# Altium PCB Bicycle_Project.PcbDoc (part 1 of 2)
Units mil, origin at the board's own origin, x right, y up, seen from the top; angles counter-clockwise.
Board outline 2480.32 x 3188.98 mil, 2 copper layers (Top Layer, Bottom Layer), stack 35.085 mil thick; 108 components, 96 nets, 359 pads, 129 vias.
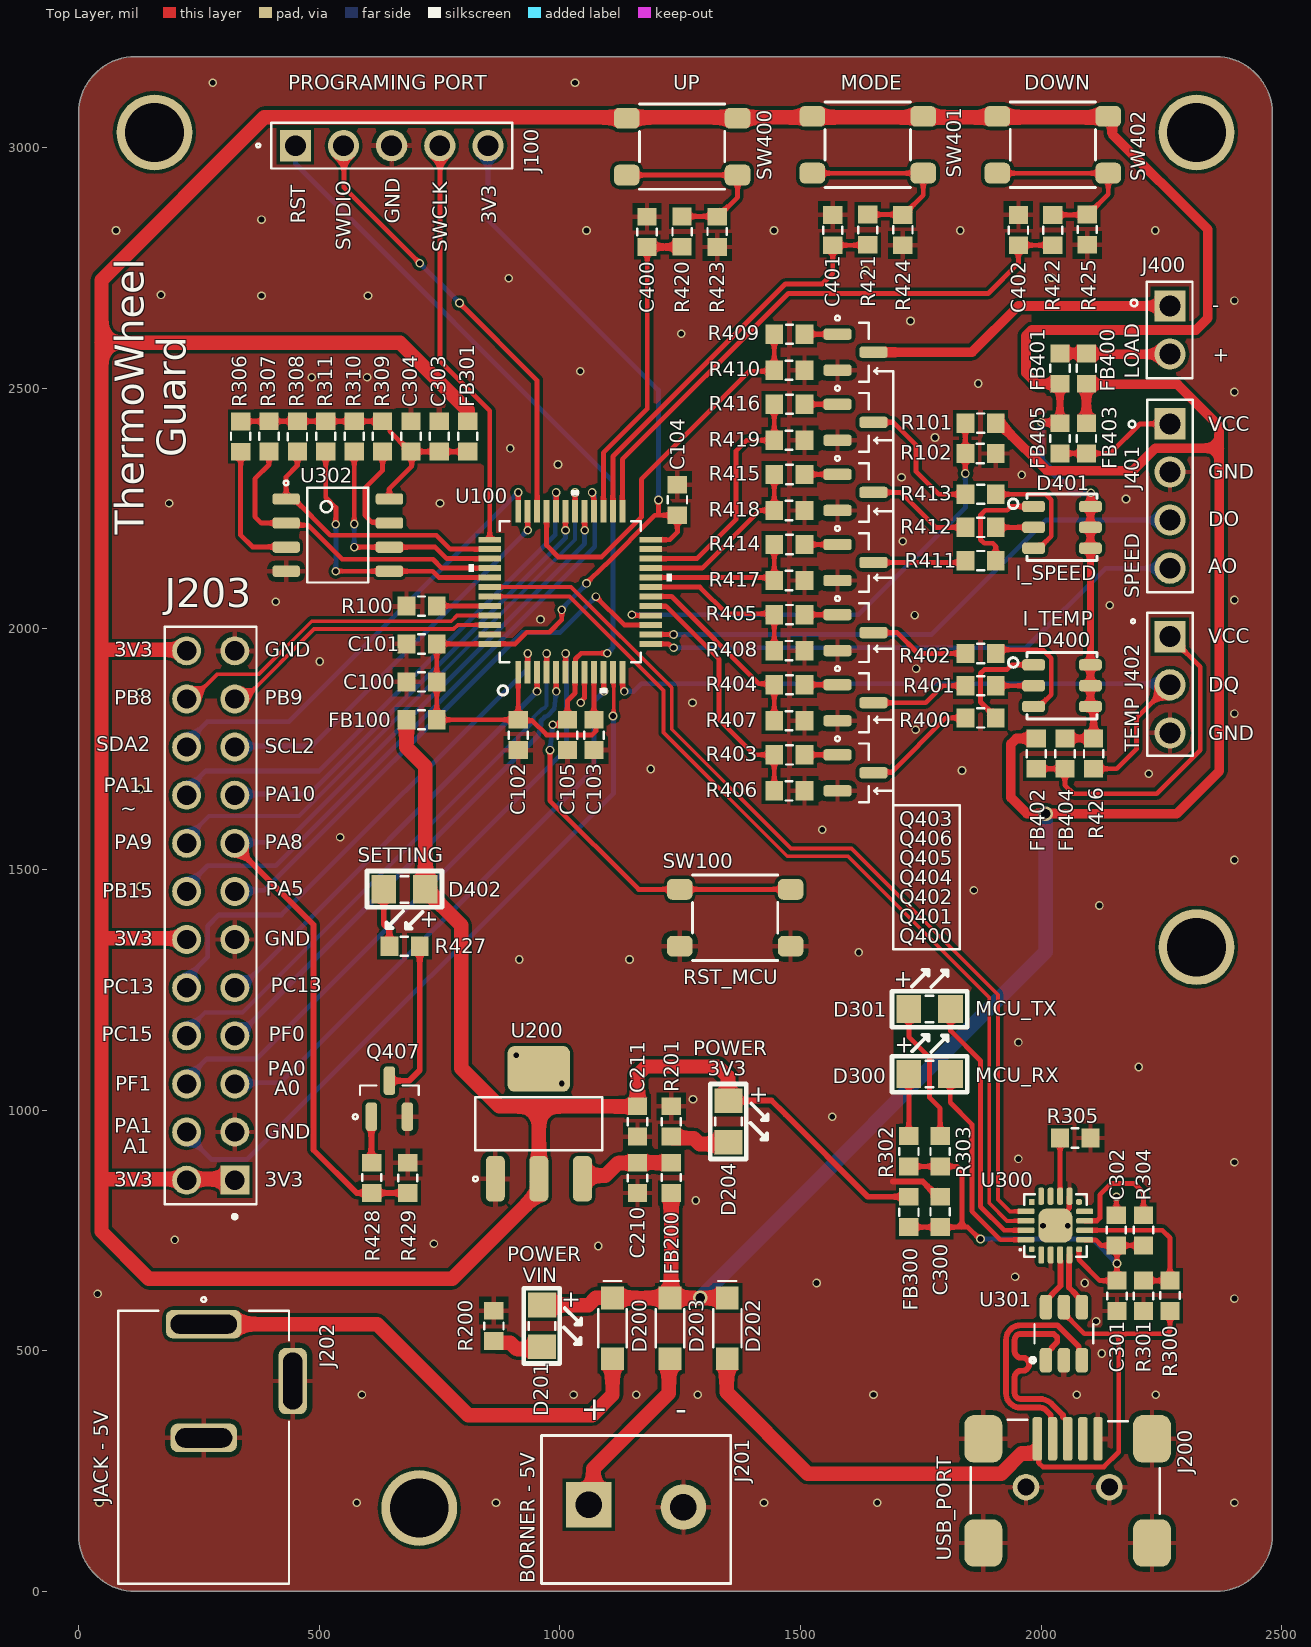
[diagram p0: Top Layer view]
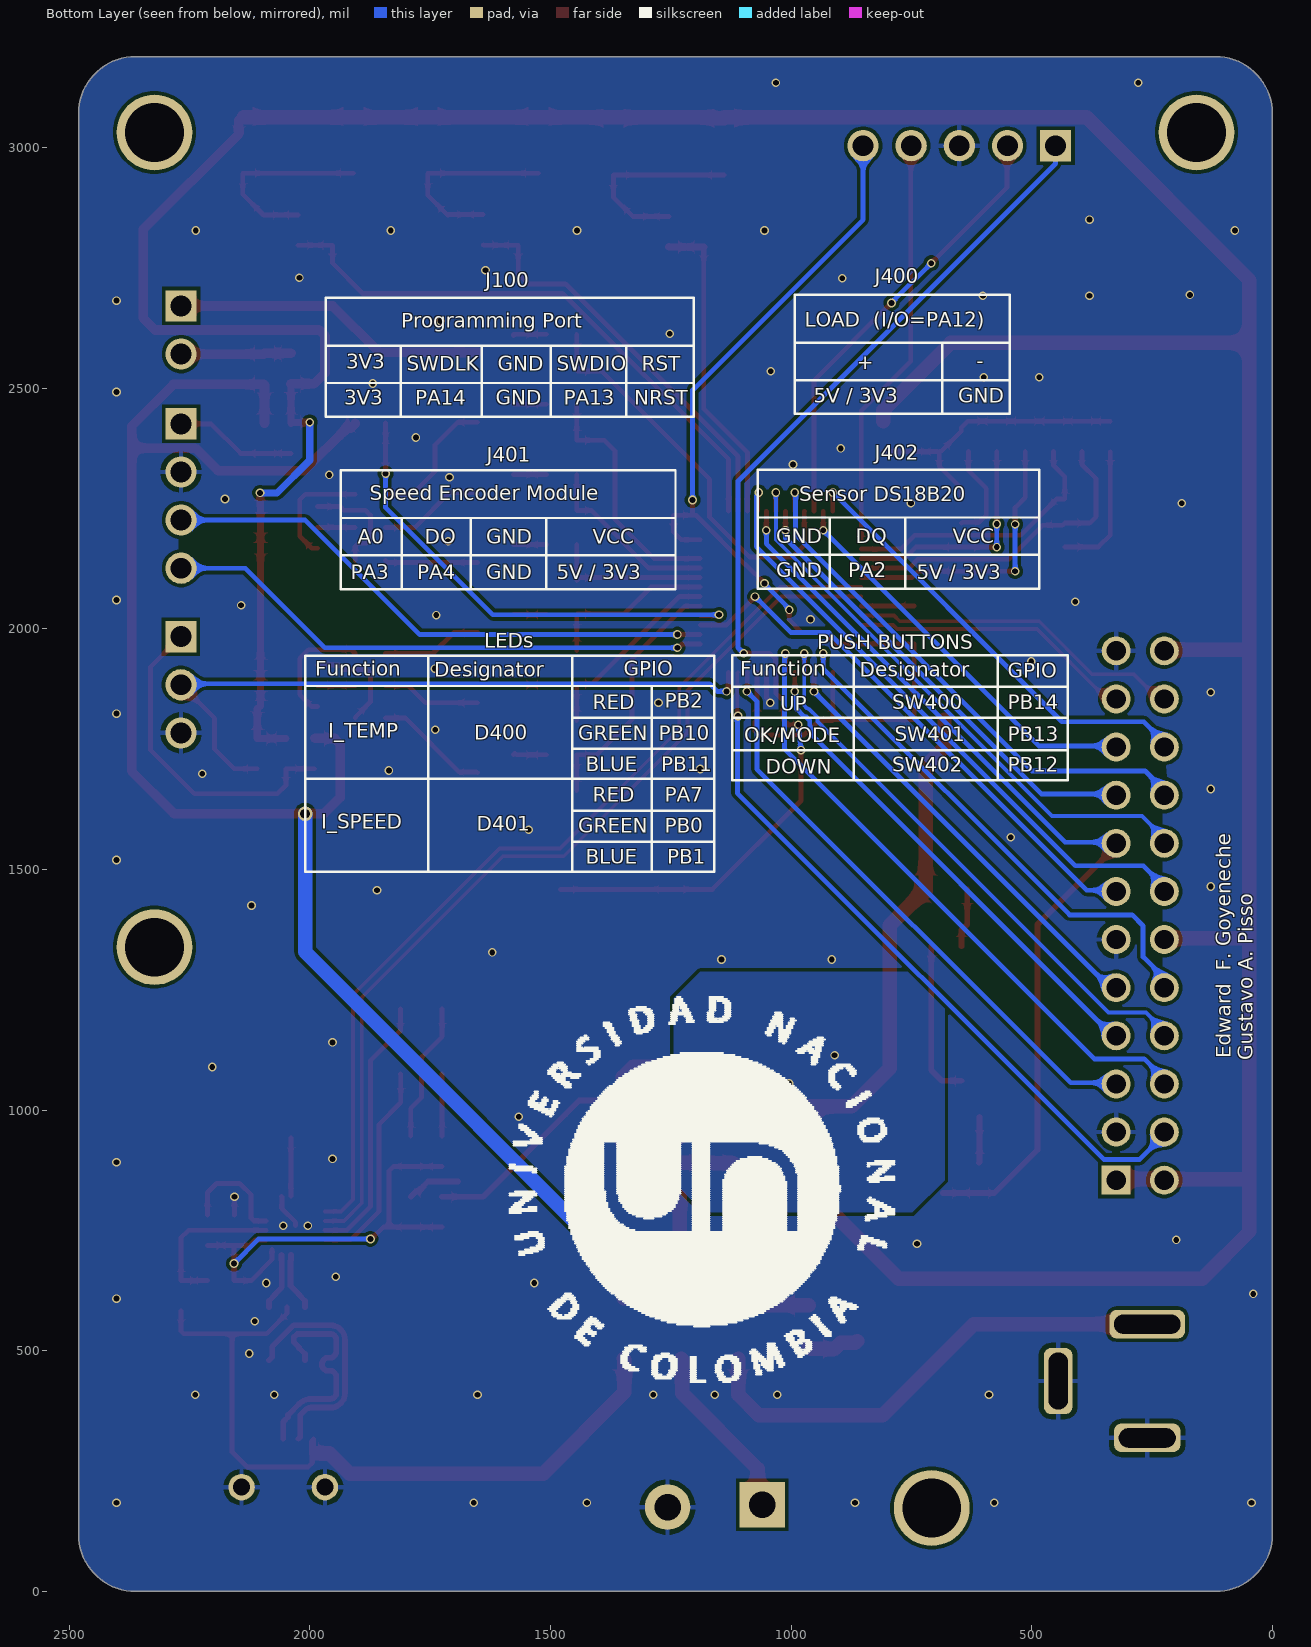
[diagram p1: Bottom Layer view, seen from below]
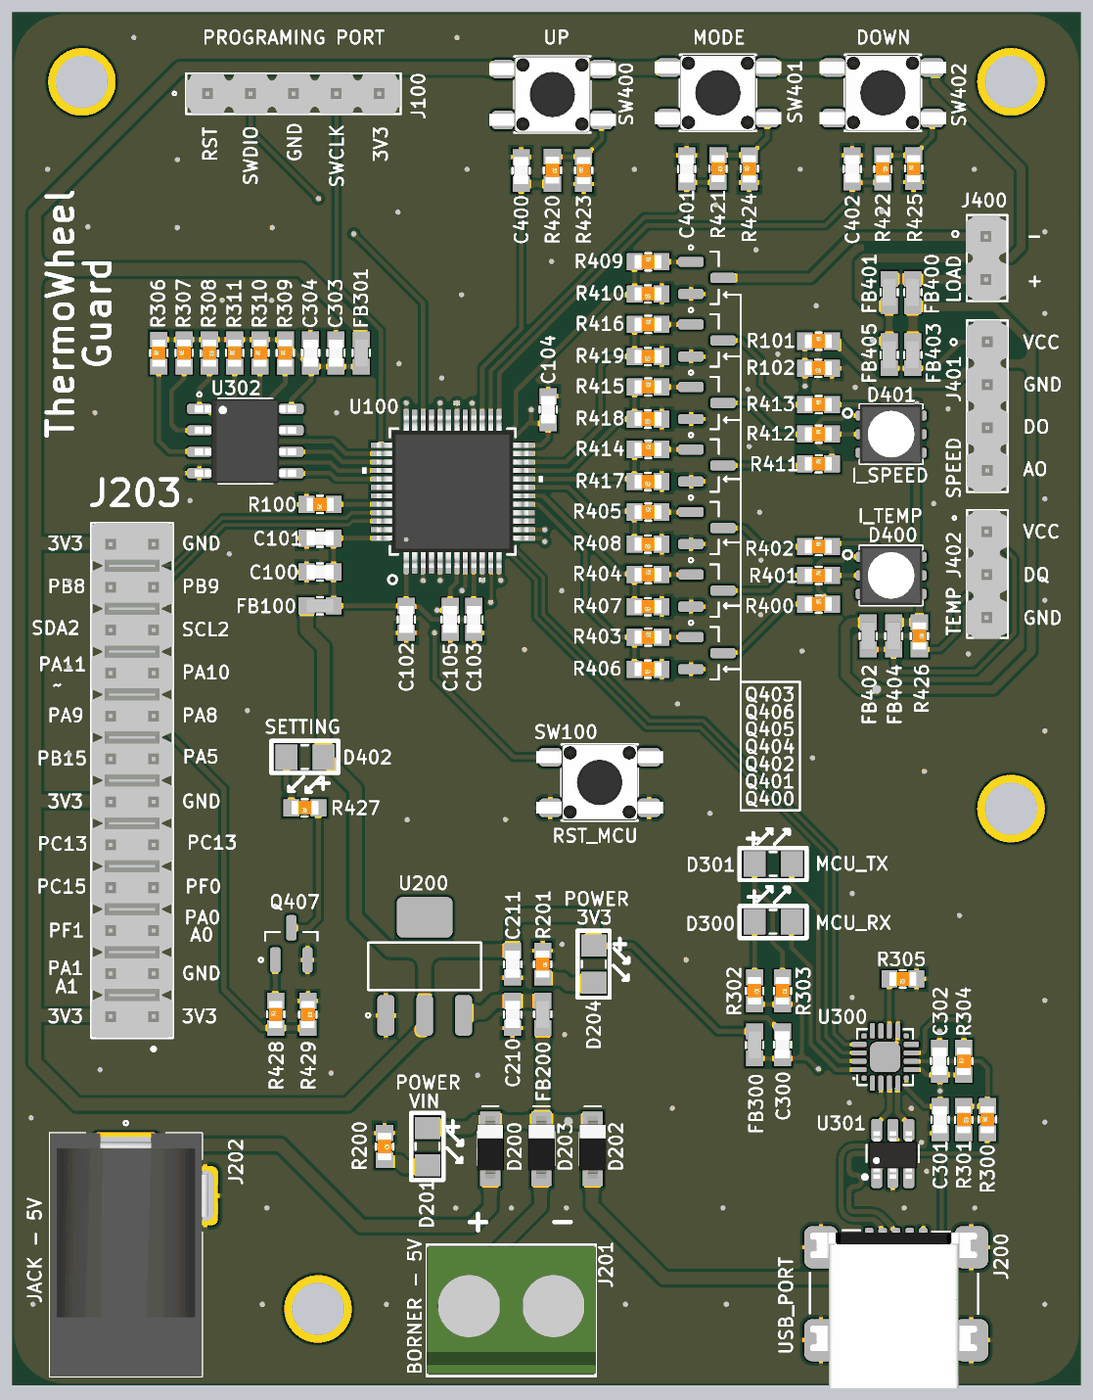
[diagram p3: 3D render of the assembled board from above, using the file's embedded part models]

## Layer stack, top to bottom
Top Solder: solder mask 0.4, Solder Resist, Dk 3.5
Top Layer: signal copper 1.4
Dielectric 1: dielectric 32.285, FR-4, Dk 4.8
Bottom Layer: signal copper 1.4
Bottom Solder: solder mask 0.4, Solder Resist, Dk 3.5

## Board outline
0,118.11 0,3070.87 cw(c118.11,3070.87) 118.11,3188.98 2362.2,3188.98 cw(c2362.2,3070.87) 2480.32,3070.87 2480.32,118.11 cw(c2362.2,118.11) 2362.2,0 118.11,0 cw(c118.11,118.11)

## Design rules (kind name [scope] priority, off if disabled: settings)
Clearance Clearance_D_P [(InNet('D_N') OR InNet('D_P') OR InNet('USB_D_N') OR InNet('USB_D_P'))] p1: gap=6 ignorepadtopadclearanceinfootprint=FALSE
Clearance [All] p2: gap=7 ignorepadtopadclearanceinfootprint=FALSE
DiffPairsRouting [All] p1: maxlimit=6 minlimit=6 mostfreqgap=6 toplayer_minwidth=12 toplayer_maxwidth=12 toplayer_prefwidth=12 bottomlayer_minwidth=12 bottomlayer_maxwidth=12 bottomlayer_prefwidth=12 maxuncoupledlength=500
HoleSize [All] p1: absolutevalues=TRUE maxlimit=1000 minlimit=12 maxpercent=80.000 minpercent=20.000
HoleToHoleClearance [All] p1: gap=12 allowstackedmicrovias=TRUE
MatchedLengths USB_L [InDifferentialPairClass('All Differential Pairs')] p1: tolerance=25 checknetsindiffpair=TRUE checkdiffpairvsdiffpair=FALSE checkxsignals=FALSE checkothers=FALSE
MinimumSolderMaskSliver [All] p1: minsoldermaskwidth=1
NetAntennae [All] p1 off: netantennaetolerance=0
PolygonConnect PolygonConnect_GND [IsVia] p1: connectstyle=Direct reliefconductorwidth=10 reliefentries=4 polygonreliefangle="90 Angle" airgapwidth=10
PolygonConnect [All] p2: connectstyle=Relief reliefconductorwidth=10 reliefentries=4 polygonreliefangle="90 Angle" airgapwidth=10
RoomDefinition Power [InComponentClass('Power')] p1: confinementstyle=ConfineIn formatcopy=TRUE lockcomponents=FALSE outline -1000,-1000 5615,-1000 5615,3730 -1000,3730
RoomDefinition MCU [InComponentClass('MCU')] p2: confinementstyle=ConfineIn formatcopy=TRUE lockcomponents=FALSE outline -1000,-1000 5785,-1000 5785,3635 -1000,3635
RoomDefinition IN_OUT [InComponentClass('IN_OUT')] p3: confinementstyle=ConfineIn formatcopy=TRUE lockcomponents=FALSE outline -1000,-1000 6480,-1000 6480,3255.91 -1000,3255.91
RoomDefinition Communication [InComponentClass('Communication')] p4: confinementstyle=ConfineIn formatcopy=TRUE lockcomponents=FALSE outline -1000,-1000 6120,-1000 6120,3450 -1000,3450
RoutingVias [All] p1: holewidth=12 width=18 viastyle="Through Hole" minholewidth=12 minwidth=18 maxholewidth=44 maxwidth=50
SilkToSilkClearance [All] p1: silktosilkclearance=1
SilkToSolderMaskClearance [IsPad] p1: minsilkscreentomaskgap=0.1 clearancetoexposedcopper=TRUE
SolderMaskExpansion [All] p1: expansion=4 istentingtop=FALSE
Width [All] p1: maxlimit=200 minlimit=8 preferedwidth=10
23 further rules are at their usual default settings.

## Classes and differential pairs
component class Power: C210 C211 D200 D201 D202 D203 D204 FB200 J200 J201 J202 J203 R200 R201 U200
component class MCU: C100 C101 C102 C103 C104 C105 FB100 J100 R100 R101 R102 SW100 U100
component class IN_OUT: C400 C401 C402 D400 D401 D402 FB400 FB401 FB402 FB403 FB404 FB405 J400 J401 J402 Q400 Q401 Q402 Q403 Q404 Q405 Q406 Q407 R400 R401 R402 R403 R404 R405 R406 R407 R408 R409 R410 R411 R412 R413 R414 R415 R416 R417 R418 R419 R420 R421 R422 R423 R424 R425 R426 R427 R428 R429 SW400 SW401 SW402
component class Communication: C300 C301 C302 C303 C304 D300 D301 FB300 FB301 R300 R301 R302 R303 R304 R305 R306 R307 R308 R309 R310 R311 U300 U301 U302
differential pair D: +D_P -D_N
differential pair USB_D: +USB_D_P -USB_D_N

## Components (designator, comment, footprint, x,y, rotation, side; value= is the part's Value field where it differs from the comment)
C100 "22uF 6V3" 0603_cap 712.6,1889.76 r180 top value=22uF
C101 "0.1uF 50V" 0603_cap 712.6,1968.5 r180 top value=0.1uF
C102 "0.1uF 50V" 0603_cap 913.39,1779.52 r270 top value=0.1uF
C103 "0.1uF 50V" 0603_cap 1070.87,1779.52 r270 top value=0.1uF
C104 "0.1uF 50V" 0603_cap 1244.09,2267.72 r90 top value=0.1uF
C105 "10uF 10V" 0603_cap 1015.75,1779.52 r270 top value=10uF
C210 "10uF 10V" 0603_cap 1161.3,859.25 r270 top value=10uF (schematic designator C200)
C211 "22uF 6V3" 0603_cap 1161.3,976.38 r270 top value=22uF (schematic designator C201)
C300 "10uF 10V" 0603_cap 1790.08,788.38 r90 top value=10uF
C301 "0.1uF 50V" 0603_cap 2157.48,614.17 r270 top value=0.1uF
C302 "0.1uF 50V" 0603_cap 2156.2,750.16 r90 top value=0.1uF
C303 "10uF 10V" 0603_cap 749.45,2399.8 r90 top value=10uF
C304 "0.1uF 50V" 0603_cap 690.47,2399.8 r90 top value=0.1uF
C400 "1uF 50V" 0603_cap 1181.1,2824.8 r270 top value=1uF
C401 "1uF 50V" 0603_cap 1566.93,2828.74 r270 top value=1uF
C402 "1uF 50V" 0603_cap 1952.76,2828.74 r270 top value=1uF
D200 "40V 1A" SOD_123 1109.31,546.5 r270 top
D201 "2V" 0805_LED 962.8,551.65 r270 top
D202 "40V 1A" SOD_123 1347.8,546.5 r270 top
D203 "40V 1A" SOD_123 1228.55,546.5 r270 top
D204 "2V" 0805_LED 1350.39,976.38 r270 top
D300 "2V" 0805_LED 1768.39,1075 r0 top
D301 "2.9V" 0805_LED 1768.39,1210 r0 top
D400 "SPEED" RGB_NS_3.5X3.7 2043.31,1881.89 r0 top
D401 "TEMPERATURE" RGB_NS_3.5X3.7 2043.31,2210.91 r0 top
D402 "2V" 0805_LED 677.17,1458.66 r180 top
FB100 "60OHM 2A" 0603_fb 712.6,1811.02 r180 top value="60 OHM"
FB200 "60OHM 2A" 0603_fb 1231.3,859.25 r90 top value="60 OHM"
FB300 "60OHM 2A" 0603_fb 1725.08,788.38 r270 top value="60 OHM"
FB301 "60OHM 2A" 0603_fb 808.42,2399.8 r90 top value="60 OHM"
FB400 "60OHM 2A" 0603_fb 2094.02,2540.91 r90 top value="60 OHM"
FB401 "60OHM 2A" 0603_fb 2039.02,2540.91 r90 top value="60 OHM"
FB402 "60OHM 2A" 0603_fb 1989.96,1740.91 r270 top value="60 OHM"
FB403 "60OHM 2A" 0603_fb 2094.02,2395.91 r270 top value="60 OHM"
FB404 "60OHM 2A" 0603_fb 2049.49,1740.91 r270 top value="60 OHM"
FB405 "60OHM 2A" 0603_fb 2039.02,2395.91 r270 top value="60 OHM"
J100 "JTAG" CON_5X1_TH_2.54MM 650.39,3003.94 r0 top
J200 "USB Mini B" CON_5x1_SMD_miniUSB_B 2055.12,208.66 r0 top
J201 "VIN_5V" CON_2x1_TH_5MM 1158.21,170 r0 top
J202 "PWR JACK 2.1mm" CON_POWER_BARREL_2.1MM_3CONN 259.84,437.01 r0 top
J203 "10129381-924001BLF" CON_2x12_th_2.54MM 324.41,854.33 r90 top
J400 "LOAD" CON_2X1_TH_2.54MM 2267,2621 r270 top
J401 "SPEED" CON_4X1_TH_2.54MM 2267.59,2276 r270 top
J402 "TEMP" CON_3X1_TH_2.54MM 2267.72,1883.77 r270 top
Q400 "N CH" SOT_23_3 1614.17,1700.79 r0 top
Q401 "N CH" SOT_23_3 1614.17,1846.46 r0 top
Q402 "N CH" SOT_23_3 1614.17,1992.13 r0 top
Q403 "N CH" SOT_23_3 1614.17,2574.8 r0 top
Q404 "N CH" SOT_23_3 1614.17,2137.8 r0 top
Q405 "N CH" SOT_23_3 1614.17,2283.46 r0 top
Q406 "N CH" SOT_23_3 1614.17,2429.13 r0 top
Q407 "N CH" SOT_23_3 645.67,1023.62 r90 top
R100 "10k 1/10W" 0603_res 712.6,2047.24 r180 top value=10k
R101 "5k1 1/10W" 0603_res 1874.02,2427.41 r0 top value=5k1
R102 "10k 1/10W" 0603_res 1874.02,2364.41 r180 top value=10k
R200 "220R 1/10W" 0603_res 862.8,551.65 r270 top value=220R
R201 "100R 1/10W" 0603_res 1231.3,976.38 r270 top value=100R
R300 "5k1 1/10W" 0603_res 2267.72,614.17 r90 top value=5k1
R301 "10k 1/10W" 0603_res 2212.6,614.17 r270 top value=10k
R302 "100R 1/10W" 0603_res 1725.08,914.38 r270 top value=100R
R303 "33R 1/10W" 0603_res 1790.08,914.38 r270 top value=33R
R304 "10k 1/10W" 0603_res 2212.6,750.16 r90 top value=10k
R305 "3k3 1/10W" 0603_res 2070.87,941.93 r180 top value=3k3
R306 "10k 1/10W" 0603_res 336.61,2399.61 r90 top value=10k
R307 "10k 1/10W" 0603_res 395.59,2399.8 r90 top value=10k
R308 "10k 1/10W" 0603_res 454.57,2399.8 r270 top value=10k
R309 "10k 1/10W" 0603_res 631.5,2399.8 r90 top value=10k
R310 "10k 1/10W" 0603_res 572.52,2399.8 r90 top value=10k
R311 "10k 1/10W" 0603_res 513.54,2399.8 r90 top value=10k
R400 "52R3 1/10W" 0603_res 1874.02,1814.96 r0 top value=52R3
R401 "24R 1/10W" 0603_res 1874.01,1881.89 r0 top value=24R
R402 "30 1/10W" 0603_res 1874.02,1948.82 r0 top value=30R
R403 "1k 1/10W" 0603_res 1476.89,1738.19 r0 top value=1k
R404 "1k 1/10W" 0603_res 1476.89,1883.86 r0 top value=1k
R405 "1k 1/10W" 0603_res 1476.89,2029.53 r0 top value=1k
R406 "10k 1/10W" 0603_res 1476.89,1663.39 r180 top value=10k
R407 "10k 1/10W" 0603_res 1476.89,1809.06 r180 top value=10k
R408 "10k 1/10W" 0603_res 1476.89,1954.72 r180 top value=10k
R409 "1k 1/10W" 0603_res 1476.89,2612.2 r0 top value=1k
R410 "10k 1/10W" 0603_res 1476.89,2537.4 r180 top value=10k
R411 "52R3 1/10W" 0603_res 1874.02,2141.73 r0 top value=52R3
R412 "24R 1/10W" 0603_res 1874.02,2210.91 r0 top value=24R
R413 "30 1/10W" 0603_res 1874.02,2279.53 r0 top value=30R
R414 "1k 1/10W" 0603_res 1476.89,2175.39 r0 top value=1k
R415 "1k 1/10W" 0603_res 1476.89,2320.77 r0 top value=1k
R416 "1k 1/10W" 0603_res 1476.89,2466.54 r0 top value=1k
R417 "10k 1/10W" 0603_res 1476.89,2100.39 r180 top value=10k
R418 "10k 1/10W" 0603_res 1476.89,2245.96 r180 top value=10k
R419 "10k 1/10W" 0603_res 1476.89,2391.73 r180 top value=10k
R420 "1k 1/10W" 0603_res 1253.94,2825.51 r270 top value=1k
R421 "1k 1/10W" 0603_res 1639.76,2829.45 r270 top value=1k
R422 "1k 1/10W" 0603_res 2024.25,2828.74 r270 top value=1k
R423 "10k 1/10W" 0603_res 1326.77,2824.8 r90 top value=10k
R424 "10k 1/10W" 0603_res 1712.6,2828.74 r90 top value=10k
R425 "10k 1/10W" 0603_res 2095.75,2829.45 r90 top value=10k
R426 "4k7 1/10W" 0603_res 2109.02,1740.91 r270 top value=4k7
R427 "100R 1/10W" 0603_res 677.17,1340.55 r180 top value=100R
R428 "1k 1/10W" 0603_res 609.19,859.25 r90 top value=1k
R429 "10k 1/10W" 0603_res 684,859.25 r270 top value=10k
SW100 "RST_MCU" Sw_PUSH_4.5x4.5x5mm 1364.17,1399.61 r0 top
SW400 "UP" Sw_PUSH_4.5x4.5x5mm 1253.94,3001.97 r180 top
SW401 "MODE" Sw_PUSH_4.5x4.5x5mm 1639.76,3005.91 r180 top
SW402 "DOWN" Sw_PUSH_4.5x4.5x5mm 2024.25,3005.91 r180 top
U100 "STM32F030C8T6TR" LQFP48_7x7mm 1021.54,2077.05 r90 top locked
U200 "AMS1117-3.3" SOT_223 956.3,971.38 r90 top
U300 "CP2102N-A02-GQFN20R" WFQFN_20_EP_3X3MM 2029.45,760 r90 top
U301 "USBLC6-2SC6" SOT_23_6 2047.24,535.43 r90 top
U302 "ZD25WQ16BTIGR" SOIC_8_3.9mm 538.43,2194.8 r0 top

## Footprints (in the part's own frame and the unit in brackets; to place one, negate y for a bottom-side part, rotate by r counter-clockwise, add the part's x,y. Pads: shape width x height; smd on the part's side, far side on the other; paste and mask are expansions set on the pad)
0603_cap [mil]
  rect 37x40 smd: 1(-31.5,0) 2(31.5,0)
  silkscreen extent -7,-20 8,20, body extent -31,-17 31,17, height 34
0603_fb [mil]
  rect 37x40 smd: 1(-31.5,0) 2(31.5,0)
  silkscreen extent -7,-20 8,20, body extent -32,-16 31,16, height 32
0603_res [mil] "1608 Metric / 20190225 / C-A.Serna.A"
  rect 37x40 smd: 1(-31.5,0) 2(31.5,0)
  silkscreen extent -7,-20 8,20, body extent -31,-16 32,16, height 12
0805_LED [mm]
  rect 1.3x1.5 smd: 1(-1.1,0) 2(1.1,0)
  silkscreen extent -1.98,-0.97 1.98,2.07, body extent -1,-0.62 1,0.63, height 1.1
CON_2X1_TH_2.54MM [mm]
  rect 1.65x1.65 / inner round 1.65 / far side rect 1.65x1.65 hole 1.1: 1(-1.27,0.015)
  round 1.65 hole 1.1: 2(1.27,0.015)
  silkscreen extent -2.54,-2.06 2.54,1.2, body extent -2.54,-1.27 2.54,1.14, height 8.18
CON_2x1_TH_5MM [mm]
  rect 2.4x2.4 hole 1.4: 1(-2.5,0.254)
  round 2.4 hole 1.4: 2(2.5,0.127)
  silkscreen extent -5,-3.9 5,3.9, body extent -5,-3.75 5,3.75, height 11.5
CON_2x12_th_2.54MM [mm]
  rect 1.53x1.53 hole 1.02: 01(0,0)
  round 1.53 hole 1.02: 02(0,2.54) 03(2.54,0) 04(2.54,2.54) 05(5.08,0) 06(5.08,2.54) 07(7.62,0) 08(7.62,2.54) 09(10.16,0) 10(10.16,2.54) 11(12.7,0) 12(12.7,2.54) 13(15.24,0) 14(15.24,2.54) 15(17.78,0) 16(17.78,2.54) 17(20.32,0) 18(20.32,2.54) 19(22.86,0) 20(22.86,2.54) 21(25.4,0) 22(25.4,2.54) 23(27.94,0) 24(27.94,2.54)
  silkscreen extent -2.02,-1.14 29.21,3.68, body extent -1.27,-1.14 29.21,3.68, height 8.18
CON_3X1_TH_2.54MM [mm]
  rect 1.65x1.65 / inner round 1.65 / far side rect 1.65x1.65 hole 1.1: 1(-2.54,0)
  round 1.65 hole 1.1: 2(0,0) 3(2.54,0)
  silkscreen extent -3.81,-2.05 3.75,1.2, body extent -3.81,-1.25 3.81,1.16, height 8.18
CON_4X1_TH_2.54MM [mm]
  rect 1.65x1.65 / inner round 1.65 / far side rect 1.65x1.65 hole 1.1: 1(-3.81,0)
  round 1.65 hole 1.1: 2(-1.27,0) 3(1.27,0) 4(3.81,0)
  silkscreen extent -5.08,-2.17 5.08,1.2, body extent -5.08,-1.2 5.08,1.2, height 8.18
CON_5x1_SMD_miniUSB_B [mm] "20190328 / V-A.Patino"
  rrect50% 2x2.5 smd: 0(-4.45,-2.75) 0(-4.45,2.75) 0(4.45,-2.75) 0(4.45,2.75)
  round 1.4 hole 0.889: 0(-2.2,0.2) 0(2.2,0.2)
  rrect50% 0.5x2.3 smd: 1(-1.6,2.75) 2(-0.8,2.75) 3(0,2.75) 4(0.8,2.75) 5(1.6,2.75)
  silkscreen extent -5.11,-1.2 4.85,3.76, body extent -5.1,-5.6 4.8,3.65, height 4
CON_5X1_TH_2.54MM [mm]
  rect 1.65x1.65 / inner round 1.65 / far side rect 1.65x1.65 hole 1.1: 1(-5.08,0)
  round 1.65 hole 1.1: 2(-2.54,0) 3(0,0) 4(2.54,0) 5(5.08,0)
  silkscreen extent -7.14,-1.2 6.36,1.2, body extent -6.35,-1.2 6.35,1.2, height 8.18
CON_POWER_BARREL_2.1MM_3CONN [mm]
  rrect50% 4x1.5 hole 1.016 slot 3.5 at 0 deg: 1(0,3)
  rrect50% 3.5x1.5 hole 1.016 slot 3 at 0 deg: 2(0,-3)
  rrect50% 1.5x3.5 hole 1.016 slot 3 at 90 deg: 3(4.7,0)
  silkscreen extent -4.5,-10.7 4.5,4.42, body extent -4.5,-10.7 4.9,3.7, height 11
LQFP48_7x7mm [mil]
  rect 47x12 smd paste+0 mask+1.8: 1(-167.32,108.27) 2(-167.32,88.58) 3(-167.32,68.9) 4(-167.32,49.21) 5(-167.32,29.53) 6(-167.32,9.84) 7(-167.32,-9.84) 8(-167.32,-29.53) 9(-167.32,-49.21) 10(-167.32,-68.9) 11(-167.32,-88.58) 12(-167.32,-108.27) 25(167.32,-108.27) 26(167.32,-88.58) 27(167.32,-68.9) 28(167.32,-49.21) 29(167.32,-29.53) 30(167.32,-9.84) 31(167.32,9.84) 32(167.32,29.53) 33(167.32,49.21) 34(167.32,68.9) 35(167.32,88.58) 36(167.32,108.27)
  rect 12x47 smd paste+0 mask+1.8: 13(-108.27,-167.32) 14(-88.58,-167.32) 15(-68.9,-167.32) 16(-49.21,-167.32) 17(-29.53,-167.32) 18(-9.84,-167.32) 19(9.84,-167.32) 20(29.53,-167.32) 21(49.21,-167.32) 22(68.9,-167.32) 23(88.58,-167.32) 24(108.27,-167.32) 37(108.27,167.32) 38(88.58,167.32) 39(68.9,167.32) 40(49.21,167.32) 41(29.53,167.32) 42(9.84,167.32) 43(-9.84,167.32) 44(-29.53,167.32) 45(-49.21,167.32) 46(-68.9,167.32) 47(-88.58,167.32) 48(-108.27,167.32)
  silkscreen extent -215,-211 211,211, body extent -177,-177 177,177, height 63
RGB_NS_3.5X3.7 [mm] "20220901/V-A.Patino"
  rrect50% 1.2x0.6 smd: 1(-1.5,1.1) 2(-1.5,0) 3(-1.5,-1.1) 4(1.5,-1.1) 5(1.5,0) 6(1.5,1.1)
  silkscreen extent -2.83,-1.75 1.85,1.75, body extent -1.85,-1.75 1.85,1.75, height 2.8
SOD_123 [mm] "/ 20191030 / V-A.Patino"
  rect 1.2x1.2 smd: 1(-1.6,0) 2(1.6,0)
  silkscreen extent -2.5,-0.75 1,0.75, body extent -1.93,-0.8 1.77,0.8, height 1.28
SOIC_8_3.9mm [mm]
  rrect50% 1.45x0.6 smd: 1(-2.725,1.905) 2(-2.725,0.635) 3(-2.725,-0.635) 4(-2.725,-1.905) 5(2.725,-1.905) 6(2.725,-0.635) 7(2.725,0.635) 8(2.725,1.905)
  silkscreen extent -2.85,-2.5 1.6,2.88, body extent -3.01,-2.5 3.01,2.5, height 1.73
SOT_23_3 [mm] "TO-236-3, SC-59/ 20220901 / V-A.Patino"
  rrect50% 1.5x0.6 smd: 1(-0.95,0.95) 2(-0.95,-0.95) 3(0.95,0)
  silkscreen extent -1.07,-1.55 0.7,1.92, body extent -0.7,-1.52 0.7,1.53, height 1.12
SOT_23_6 [mm] "/ 20190225 / V-A.Patino"
  rrect50% 1.3x0.65 smd: 1(-1.4,0.95) 2(-1.4,0) 3(-1.4,-0.95) 4(1.4,-0.95) 5(1.4,0) 6(1.4,0.95)
  silkscreen extent -1.52,-1.55 0.5,1.78, body extent -1.5,-1.45 1.3,1.45, height 1.45
SOT_223 [mm] "TO-261-4, TO-261AA / 20220901/ V-A.Patino"
  rrect50% 2.4x1 smd: 1(-2.9,2.3) 2(-2.9,0) 3(-2.9,-2.3)
  rrect30% 2.4x3.3 smd: 4(2.9,0)
  silkscreen extent -3.02,-3.35 1.4,3.47, body extent -1.86,-3.35 1.86,3.35, height 1.8
Sw_PUSH_4.5x4.5x5mm [mm]
  rrect50% 1.35x1.1 smd: 1(-2.925,1.5) 1(2.925,1.5) 2(-2.925,-1.5) 2(2.925,-1.5)
  silkscreen extent -2.25,-2.25 2.25,2.25, body extent -3.75,-2.25 3.75,2.25, height 3.8
WFQFN_20_EP_3X3MM [mm] "QFN_20/ 20210809/ V-A.Patino"
  rrect50% 0.3x0.3 smd: 1(-1.25,1.25) 6(-1.25,-1.25) 11(1.25,-1.25)
  rrect50% 0.9x0.3 smd: 2(-1.55,0.75) 3(-1.55,0.25) 4(-1.55,-0.25) 5(-1.55,-0.75) 12(1.55,-0.75) 13(1.55,-0.25) 14(1.55,0.25) 15(1.55,0.75)
  rrect50% 0.3x0.9 smd: 7(-0.75,-1.55) 8(-0.25,-1.55) 9(0.25,-1.55) 10(0.75,-1.55) 17(0.75,1.55) 18(0.25,1.55) 19(-0.25,1.55) 20(-0.75,1.55)
  rect 0.3x0.3 smd: 16(1.25,1.25)
  rrect50% 1.8x1.8 smd: 21(0,0)
  silkscreen extent -1.65,-1.65 1.65,1.9, body extent -1.5,-1.5 1.5,1.5, height 0.8

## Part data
C100 C211: library part Cap_22uF_0805_6V3, "6.3V 22uF X5R ±20% 0805 Multilayer Ceramic Capacitors MLCC - SMD/SMT ROHS", Manufacturer="Samsung Electro-Mechanics", Manufacturer Part Number=CL21A226MQQNNNE, Supplier Part Number 1=C5674
C101 C102 C103 C104 C301 C302 C304: library part Cap_0.1uF_0603_50V, "50V 100nF Y5V -20%~+80% 0603 Multilayer Ceramic Capacitors MLCC - SMD/SMT ROHS", Manufacturer="Walsin Tech Corp", Manufacturer Part Number=0603F104Z500CT, Supplier Part Number 1=C83060
C105 C210 C300 C303: library part Cap_10uF_0603_10V, "10V 10uF X5R ±10% 0603 Multilayer Ceramic Capacitors MLCC - SMD/SMT ROHS", Manufacturer=CCTC, Manufacturer Part Number=TCC0603X5R106K100CT, Supplier Part Number 1=C380314
C400 C401 C402: library part Cap_1uF_0603_50V, "50V 1uF X5R ±10% 0603 Multilayer Ceramic Capacitors MLCC - SMD/SMT ROHS", Manufacturer="Samsung Electro-Mechanics", Manufacturer Part Number=CL10A105KB8NNNC, Supplier Part Number 1=C15849
D200 D202 D203: library part D_Schottky_40V_1A_SOD_123F, "DIODE SCHOTTKY 40V 1A SOD123F", Manufacturer="Shanghai Prisemi Elec", Manufacturer Part Number=PSBD1DF40V1H, Supplier Part Number 1=C110730
D201 D204 D300 D402: library part LED_0805_RED, "LED RED CLEAR 0805 SMD", Manufacturer=XINGLIGHT, Manufacturer Part Number=XL-2012SURC, Supplier Part Number 1=C965812
D301: library part LED_0805_Green, "LED GREEN CLEAR 0805 SMD", Manufacturer=XINGLIGHT, Manufacturer Part Number=XL-2012UGC, Supplier Part Number 1=C965815
D400 D401: library part LED_RGB_3535_SMD, "-30℃~+85℃ RGB 110° 3535(mm) Light Emitting Diodes (LED) ROHS", Manufacturer="Foshan NationStar Optoelectronics", Manufacturer Part Number=RS-3535MWAM, Supplier Part Number 1=C842778
FB100 FB200 FB300 FB301 FB400 FB401 FB402 FB403 FB404 FB405: library part FB_60_0603_2A, "2A 1 100mΩ 60Ω@100MHz ±25% 0603 Ferrite Beads ROHS", Manufacturer=TAI-TECH, Manufacturer Part Number=HCB1608KF-600T20, Supplier Part Number 1=C369516
J100: library part Con_5X1_TH_2.54mm, "CONN HEADER VERT 5POS 2.54MM", Manufacturer="Amphenol ICC (FCI)", Manufacturer Part Number=10129378-905001BLF, Supplier Part Number 1=10129378-905001BLF-ND
J200: library part Con_Mini_USB_B, "CONN RCPT USB2.0 MINI B SMD R/A", Manufacturer="EDAC Inc.", Manufacturer Part Number=KH-MINI-SMT-5P-Cu, Supplier Part Number 1=C2688795
J201: library part Con_2x1_TH_5mm, "2POS 5MM", Manufacturer=JILN, Manufacturer Part Number=JL126-50002G01, Supplier Part Number 1=C394556
J202: library part Con_Power_Jack_2.1mm_3pins, "CONN PWR JACK 2X5.5MM SOLDER", Manufacturer=HCTL, Manufacturer Part Number=HC-DC-005-2.0T, Supplier Part Number 1=C3010533
J203: library part Con_2x12_TH_2.54mm, "CONN HEADER VERT 24POS 2.54MM", Manufacturer="Amphenol ICC (FCI)", Supplier Part Number 1=10129381-924001BLF-ND
J400: library part Con_2x1_TH_2.54mm, "CONN HEADER VERT 2POS 2.54MM", Manufacturer="Amphenol ICC (FCI)", Manufacturer Part Number=10129378-902001BLF, Supplier Part Number 1=10129378-902001BLF-ND
J401: library part Con_4X1_TH_2.54mm, "CONN HEADER VERT 4POS 2.54MM", Manufacturer="Amphenol ICC (FCI)", Manufacturer Part Number=10129378-904001BLF, Supplier Part Number 1=10129378-904001BLF-ND
J402: library part Con_3X1_TH_2.54mm, "CONN HEADER VERT 3POS 2.54MM", Manufacturer="Amphenol ICC (FCI)", Manufacturer Part Number=10129378-903001BLF, Supplier Part Number 1=10129378-903001BLF-ND
Q400 Q401 Q402 Q403 Q404 Q405 Q406 Q407: library part Q_NFET_20V_3.2A_SOT23, "MOSFET N-CH 20V SOT23", Manufacturer=Doeshare, Manufacturer Part Number=DN2302S, Supplier Part Number 1=C2931750
R100 R102 R301 R304 R306 R307 R308 R309 R310 R311 R406 R407 R408 R410 R417 R418 R419 R423 R424 R425 R429: library part Res_10k_0603_1/10W, "RES SMD 10k OHM 5% 1/10W 0603", Manufacturer=FOJAN, Manufacturer Part Number=FRC0603J103TS, Supplier Part Number 1=C2930027
R101 R300: library part Res_5k1_0603_1/10W, "RES SMD 5k1 OHM 5% 1/10W 0603", Manufacturer=FOJAN, Manufacturer Part Number="FRC0603J512 TS", Supplier Part Number 1=C2907114
R200: library part Res_220R_0603_1/10W, "RES SMD 220R OHM 5% 1/10W 0603", Manufacturer=FOJAN, Manufacturer Part Number="FRC0603J221 TS", Supplier Part Number 1=C2907127
R201 R302 R427: library part Res_100R_0603_1/10W, "RES SMD 100R OHM 5% 1/10W 0603", Manufacturer=FOJAN, Manufacturer Part Number="FRC0603J101 TS", Supplier Part Number 1=C2907089
R303: library part Res_33R_0603_1/10W, "RES SMD 33R OHM 5% 1/10W 0603", Manufacturer=FOJAN, Manufacturer Part Number="FRC0603J330 TS", Supplier Part Number 1=C2907154
R305: library part Res_3k3_0603_1/10W, "RES SMD 3k3 OHM 5% 1/10W 0603", Manufacturer=FOJAN, Manufacturer Part Number="FRC0603J332 TS", Supplier Part Number 1=C2907140
R400 R411: library part Res_52R3_0603_1/10W_1, "RES SMD 52R3 OHM 1% 1/10W 0603", Manufacturer=FOJAN, Manufacturer Part Number=FRC0603F52R3TS, Supplier Part Number 1=C2998074
R401 R412: library part Res_24R_0603_1/10W, "RES SMD 24R OHM 5% 1/10W 0603", Manufacturer=FOJAN, Manufacturer Part Number="FRC0603J240 TS", Supplier Part Number 1=C2907132
R402 R413: library part Res_30R_0603_1/10W, "RES SMD 30R OHM 1% 1/10W 0603", Manufacturer=FOJAN, Manufacturer Part Number=FRC0603F30R0TS, Supplier Part Number 1=C2907026
R403 R404 R405 R409 R414 R415 R416 R420 R421 R422 R428: library part Res_1k_0603_1/10W, "RES SMD 1k OHM 5% 1/10W 0603", Manufacturer=FOJAN, Manufacturer Part Number="FRC0603J102 TS", Supplier Part Number 1=C2907113
R426: library part Res_4k7_0603_1/10W, "RES SMD 4k7 OHM 5% 1/10W 0603", Manufacturer=FOJAN, Manufacturer Part Number="FRC0603J472 TS", Supplier Part Number 1=C2907166
SW100 SW400 SW401 SW402: library part Sw_PUSH_4.5x4.5x5.0xmm, "SWITCH TACTILE SPST-NO 0.05A 12V", Manufacturer=BZCN, Manufacturer Part Number=TSC015A05026A, Supplier Part Number 1=C2888509
U100: library part IC_STM32F030C8T6TR_LQFP48_7x7MM, "IC MCU 32BIT 64KB FLASH 48LQFP", Manufacturer=STMicroelectronics, Supplier Part Number 1=C23922
U200: library part LDO_3V3_1A_FIXED, "1A 60dB@(120Hz) Fixed 3.3V Positive 18V SOT-223 Linear Voltage Regulators (LDO) ROHS", Manufacturer="UMW(Youtai Semiconductor Co., Ltd.)", Supplier Part Number 1=C347222
U300: library part IC_SGL_USB2UART-BRIDGE_20QFN, "IC USB TO UART BRIDGE QFN20", Manufacturer="Silicon Labs", Supplier Part Number 1=C969913
U301: library part TVS_5.25V_2CH_SOT_23_6, "TVS DIODE 5.25V 17V SOT23-6", Manufacturer=STMicroelectronics, Supplier Part Number 1=C7519
U302: library part IC_FLASH_ZD25WQ16BTIGR_8SOP, "IC FLASH 16M SPI 85MHZ 8SOP", Manufacturer=Zetta, Supplier Part Number 1=C2896790

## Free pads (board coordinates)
  round 157.48 hole 122.05: 0(157.48,3031.5) 0(707.68,173.23) 0(2322.83,1338.58) 0(2322.83,3031.5)

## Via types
v1: diameter 18, hole 12, Top Layer to Bottom Layer, tented both sides, 127 vias
v2: diameter 30, hole 20, Top Layer to Bottom Layer, tented both sides, 2 vias

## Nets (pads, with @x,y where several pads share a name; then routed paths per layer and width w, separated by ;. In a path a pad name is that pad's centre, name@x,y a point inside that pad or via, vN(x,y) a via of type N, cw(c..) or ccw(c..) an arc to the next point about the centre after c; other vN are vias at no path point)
3V3: C211.1 D204.1 D400.4 D400.5 D400.6 D401.4 D401.5 D401.6 D402.1 FB100.2 FB300.1 FB301.2 FB401.1 FB404.1 FB405.1 J203.01 J203.02 J203.12 J203.24 R426.1 SW400.2 SW401.2 SW402.2 U200.2 | length 10772.2
  Top Layer w12: D204.1@1350.39,1019.68 1439.96,1019.68 1468.5,991.14 1639.77,819.88 FB300.1@1725.08,819.88
  Top Layer w15: v1(2000,2429.13) 2000.57,2428.56 2037.86,2428.56 FB405.1@2039.02,2427.41 FB401.1@2039.02,2509.41 ; FB404.1@2049.49,1772.41 R426.1@2109.02,1772.41 2109.02,1834.27 2104.7,1838.58 D400.4@2102.36,1838.58 D400.5@2102.36,1881.89 D400.6@2102.36,1925.2 D401.4@2102.36,2167.6 D401.5@2102.36,2210.91 D401.6@2102.36,2254.21 2102.85,2254.7 2102.85,2281.99 v1(2103.35,2282.48)
  Top Layer w20: FB401.1@2039.02,2509.41 1990.59,2509.41 1968.5,2531.5 1968.5,2609.28 1980.22,2621 2321.79,2621 2346.46,2645.67 2346.46,2829.72 2147.47,3028.71 2147.47,3056.9 SW402.2@2139.41,3064.96
  Top Layer w30: J203.12@216.54,1356.69 49.05,1356.69 47.47,1358.27 ; J203.24@216.54,1956.69 51.41,1956.69 47.47,1952.76 ; J203.01@316.54,856.69 216.54,856.69 49.83,856.69 47.47,854.33 ; FB100.2@681.1,1811.02 681.1,1753.94 720.47,1714.57 720.47,1454.72 731.06,1444.13 735,1444.13 795.28,1383.86 795.28,1086.61 874.01,1007.88 956.3,1007.88 ; FB301.2@808.42,2431.3 808.42,2453.8 667.74,2594.49 47.47,2594.49 ; SW400.2@1138.78,3061.02 SW400.2@1158.46,3061.02 ; SW400.2@1138.78,3062.99 385.83,3062.99 47.47,2724.64 47.47,2594.49 ; SW400.2@1158.46,3062.99 1369.09,3062.99 1524.61,3062.99 1754.92,3062.99 1909.09,3062.99 SW402.2@2137.44,3062.99 ; D204.1@1350.39,1019.68 1349.41,1020.67 1349.41,1068.9 1327.76,1090.55 1178.87,1090.55 1161.3,1072.98 C211.1@1161.3,1007.88 956.3,1007.88 ; 47.47,854.33 47.47,1358.27 ; 47.47,854.33 47.47,747.8 145.67,649.61 776.26,649.61 956.3,829.65 U200.2@956.3,857.2 956.3,1007.88 ; 47.47,1358.27 47.47,1952.76 ; 47.47,1952.76 47.47,2594.49
  Bottom Layer w15: v1(2000,2429.13) 2000,2350.39 2067.91,2282.48 v1(2103.35,2282.48)
"3V3 _MCU": C100.1 C101.1 C102.1 C103.1 C104.1 FB100.1 J100.5 U100.1 U100.9 U100.24 U100.48 | length 2357.8
  Top Layer w8: 1093.24,2132.61 1093.87,2132.61
  Top Layer w10: U100.1@913.27,1909.72 913.27,1811.14 C102.1@913.39,1811.02 ; v1(1003.94,2039.37) 1003.94,2018.7 978.35,1993.11 931.1,1993.11 906.77,1968.78 U100.48@854.21,1968.78 744.37,1968.78 C101.1@744.1,1968.5 C100.1@744.1,1889.76 FB100.1@744.1,1811.02 C102.1@913.39,1811.02 ; v1(1055.12,2094.49) 1093.24,2132.61 ; U100.9@1070.75,1909.72 1070.75,1811.14 C103.1@1070.87,1811.02 1074.8,1807.09 1074.8,1787.4 1066.93,1779.52 972.44,1779.52 942.53,1809.44 914.97,1809.44 C102.1@913.39,1811.02 ; 1093.87,2132.61 1197.49,2236.22 1204.72,2236.22 ; U100.24@1188.86,2185.32 1228.62,2185.32 1244.09,2200.79 C104.1@1244.09,2236.22 ; v1(1204.72,2267.72) 1204.72,2236.22 ; C104.1@1236.22,2236.22 1204.72,2236.22
  Bottom Layer w10: J100.5@850.39,3005.54 J100.5@850.39,3003.94 850.39,2850.39 1204.72,2496.06 v1(1204.72,2267.72) ; v1(1003.94,2039.37) 1003.94,2041.34 1055.12,2092.52 v1(1055.12,2094.49)
3V3_CP21: C300.1 C301.1 C302.1 FB300.2 R302.2 R303.2 R304.1 U300.6 U300.7 | length 1013.6
  Top Layer w10: FB300.2@1725.08,756.88 C300.1@1790.08,756.88 1835.5,756.88 ; R302.2@1725.08,882.88 R303.2@1790.08,882.88 1825.78,882.88 1835.5,873.16 1835.5,756.88 ; v1(1874.02,732.28) 1871.85,732.28 1847.26,756.88 1835.5,756.88 ; U300.6@2078.66,710.79 2078.66,689.06 2122.04,645.67 C301.1@2157.48,645.67 v1(2157.48,681.1) 2157.48,717.38 C302.1@2156.2,718.66 ; U300.7@2090.47,730.47 2090.59,730.36 2113.46,730.36 2125.16,718.66 C302.1@2156.2,718.66 ; R304.1@2212.6,718.66 C302.1@2156.2,718.66
  Bottom Layer w10: v1(1874.02,732.28) 2106.3,732.28 v1(2157.48,681.1)
3V3_FLASH: C303.1 C304.1 FB301.1 R306.2 R307.2 R308.1 R309.2 R310.2 R311.2 U302.8 | length 614.9
  Top Layer w10: R306.2@336.61,2431.11 336.81,2431.3 R307.2@395.59,2431.3 R308.1@454.57,2431.3 R311.2@513.54,2431.3 R310.2@572.52,2431.3 R309.2@631.5,2431.3 633,2431.3 646.5,2417.8 646.5,2410.78 688.97,2368.3 C304.1@690.47,2368.3 691.93,2366.85 691.93,2337.6 645.71,2291.38 U302.8@645.71,2269.8 ; C304.1@695.93,2368.3 C303.1@749.45,2368.3 FB301.1@808.42,2368.3
B_SPEED_LED: R405.1 R408.2 U100.19 | length 355.1
  Top Layer w10: U100.19@1188.86,2086.89 1291.06,2086.89 1346.46,2031.5 1443.43,2031.5 R405.1@1445.39,2029.53 R408.2@1445.39,1954.72
B_TEMP_LED: R416.1 R419.2 U100.22 | length 516.7
  Top Layer w10: U100.22@1188.86,2145.94 1284.72,2145.94 1366.14,2227.36 1366.14,2370.08 1387.8,2391.73 R419.2@1445.39,2391.73 R416.1@1445.39,2466.54
D_N: U300.5 U301.4 | length 119.8
  Top Layer w12: U300.5@2058.98,698.98 2058.98,687.35 2058.13,686.51 2058.13,631.26 2072.03,617.36 2072.03,616.18 2084.65,603.56 U301.4@2084.65,590.55
D_P: U300.4 U301.6 | length 121.3
  Top Layer w12: U301.6@2009.84,590.55 2009.84,603.56 2022.44,616.16 2022.44,617.36 2040.13,635.06 2040.13,686.51 2039.29,687.35 U300.4@2039.29,698.98
EP: U200.4
  other v1: 1003.94,1055.12 909.45,1114.17
FLASH_CS: R308.2 U100.38 U302.1 | length 574.4
  Top Layer w10: R308.2@454.57,2368.3 454.57,2339.41 431.14,2315.98 U302.1@431.14,2269.8 447.87,2269.8 523.06,2194.61 743.38,2194.61 772.36,2165.63 U100.38@854.21,2165.63
FLASH_MISO: R307.1 U100.40 U302.2 | length 679.6
  Top Layer w10: R307.1@395.59,2368.3 395.59,2341.46 366.14,2312.01 366.14,2233.27 379.61,2219.8 U302.2@431.14,2219.8 435.68,2215.27 476.66,2215.27 547.32,2144.61 736.29,2144.61 754.65,2126.26 U100.40@854.21,2126.26
FLASH_MOSI: R311.1 U100.41 U302.5 | length 582.4
  Top Layer w10: R311.1@513.54,2368.3 513.54,2272.87 534.45,2251.97 v1(534.45,2217.52) ; v1(534.45,2119.8) U302.5@645.71,2119.8 735.65,2119.8 748.87,2106.57 U100.41@854.21,2106.57
  Bottom Layer w10: v1(534.45,2119.8) v1(534.45,2217.52)
FLASH_SCK: R310.1 U100.39 U302.6 | length 490.1
  Top Layer w10: v1(572.52,2169.8) U302.6@645.71,2169.8 740.86,2169.8 764.72,2145.94 U100.39@854.21,2145.94 ; v1(572.52,2217.99) R310.1@572.52,2368.3
  Bottom Layer w10: v1(572.52,2169.8) v1(572.52,2217.99)
G_SPEED_LED: R404.1 R407.2 U100.18 | length 407.3
  Top Layer w10: U100.18@1188.86,2067.2 1232.01,2067.2 1413.39,1885.83 1443.43,1885.83 R404.1@1445.39,1883.86 R407.2@1445.39,1809.06
G_TEMP_LED: R415.1 R418.2 U100.21 | length 380.9
  Top Layer w10: U100.21@1188.86,2126.26 1295.55,2126.26 1415.26,2245.96 R418.2@1445.39,2245.96 R415.1@1445.39,2320.77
